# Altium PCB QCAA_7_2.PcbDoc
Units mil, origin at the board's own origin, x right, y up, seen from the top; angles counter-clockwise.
Board outline 636.93 x 714.73 mil, 2 copper layers (Top Layer, Bottom Layer); 42 components, 40 nets, 167 pads, 57 vias.
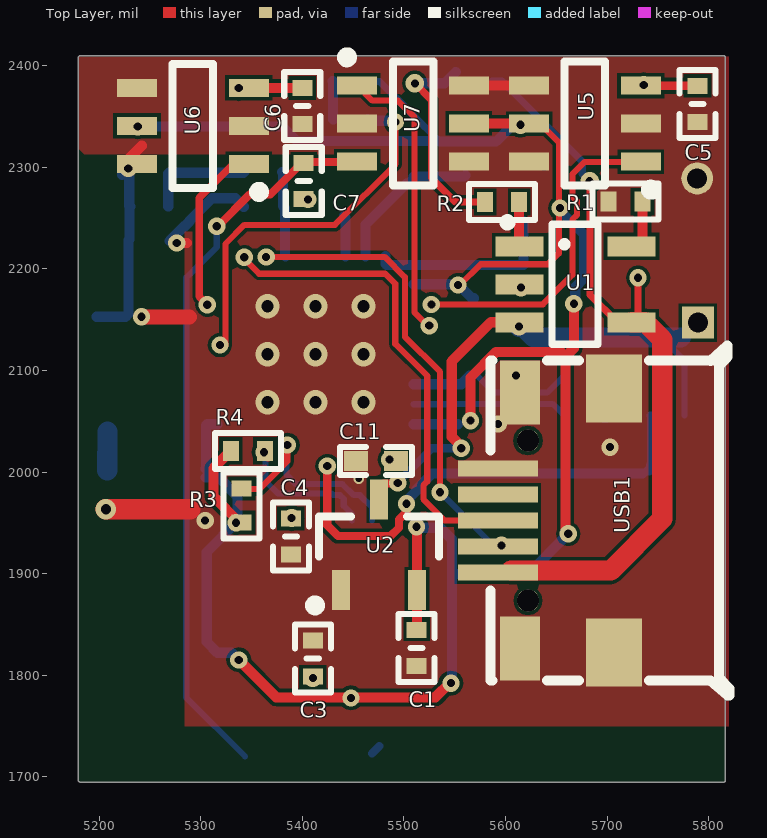
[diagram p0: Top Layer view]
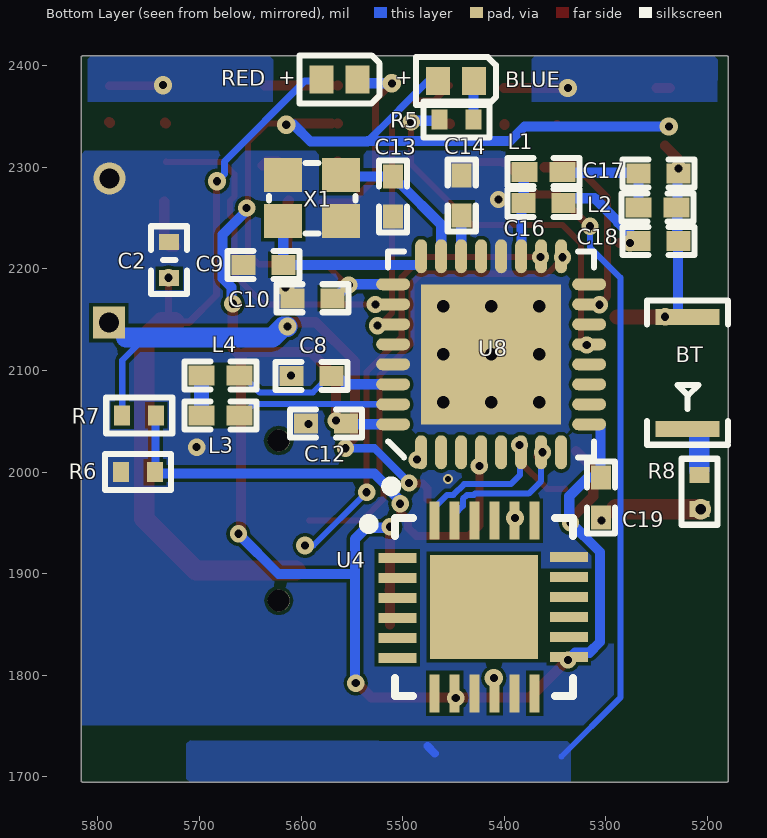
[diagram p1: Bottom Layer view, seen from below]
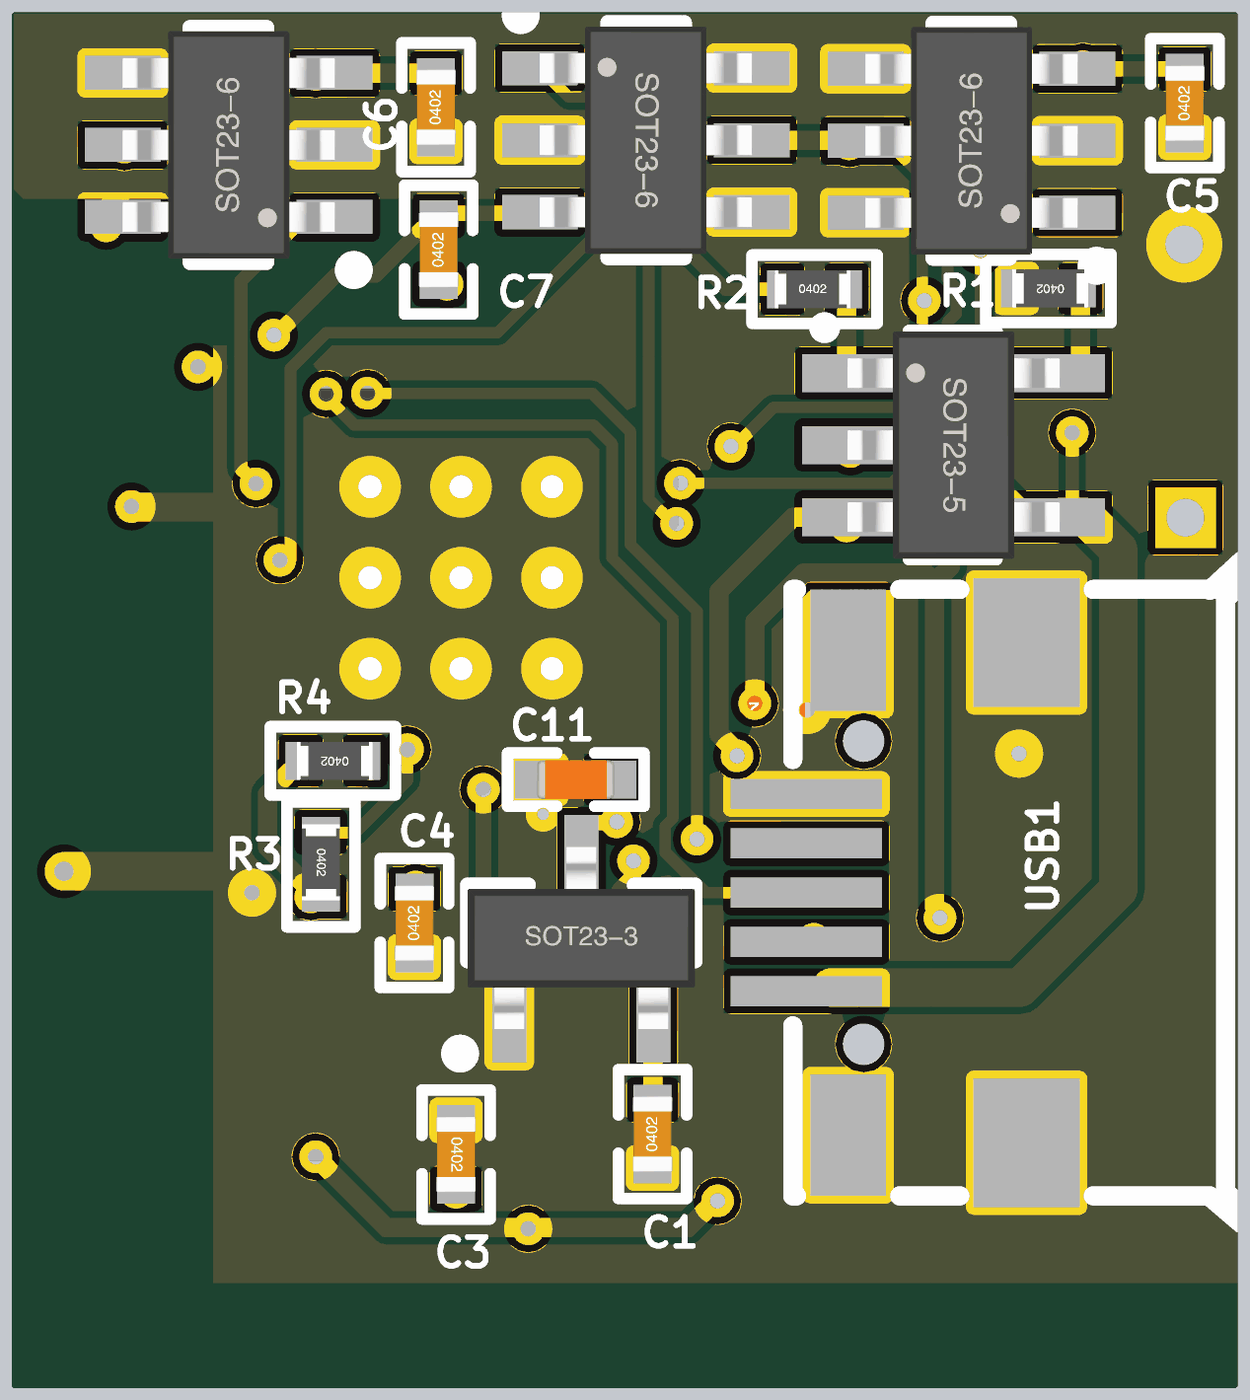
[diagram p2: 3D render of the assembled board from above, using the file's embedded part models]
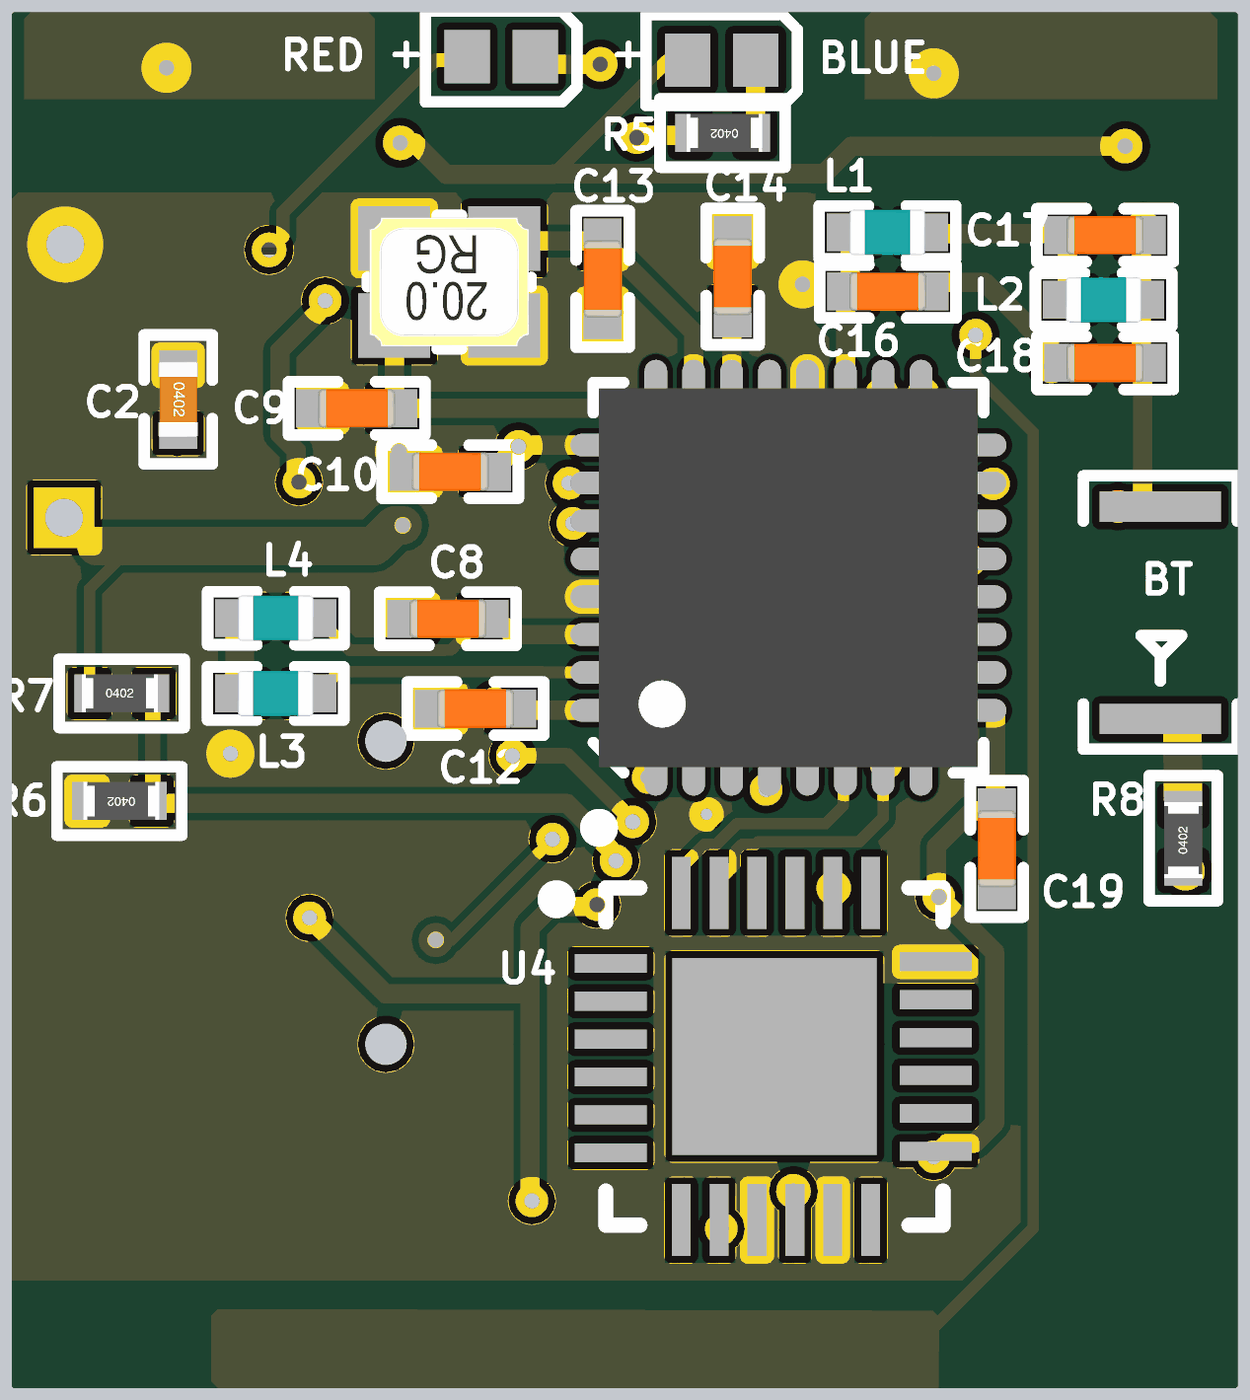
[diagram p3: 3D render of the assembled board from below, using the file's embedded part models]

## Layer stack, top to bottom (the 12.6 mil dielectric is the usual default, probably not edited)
Top Solder: solder mask 0.4, Solder Resist, Dk 3.5
Top Layer: signal copper 1.4
Dielectric 1: dielectric 12.6, FR-4, Dk 4.8
Bottom Layer: signal copper 1.4
Bottom Solder: solder mask 0.4, Solder Resist, Dk 3.5

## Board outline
5179.59,1696.5 5179.59,2408.1 cw(c5181.1,2408.1) 5180.03,2409.17 5180.13,2409.27 cw(c5181.2,2408.2) 5181.2,2409.72 5815,2409.72 cw(c5815,2408.2) 5816.52,2408.2 5816.52,1696.5 cw(c5815,1696.5) 5815,1694.98 5181.1,1694.98 cw(c5181.1,1696.5)

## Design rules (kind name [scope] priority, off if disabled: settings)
Clearance [All] p1: gap=3.5 ignorepadtopadclearanceinfootprint=TRUE except(5: Arc-Via Track-Via)
MinimumSolderMaskSliver [All] p1: minsoldermaskwidth=0
PlaneConnect [All] p1: planeconnectstyle=Direct reliefexpansion=20 reliefentries=4 reliefconductorwidth=10 reliefairgap=10
PolygonConnect [All] p1: connectstyle=Direct reliefconductorwidth=10 reliefentries=4 polygonreliefangle="90 Angle" airgapwidth=10
RoutingVias [All] p1: holewidth=28 width=50 viastyle="Through Hole" minholewidth=3 minwidth=0 maxholewidth=28 maxwidth=50
SilkToSilkClearance [All] p1: silktosilkclearance=0
SilkToSolderMaskClearance [IsPad] p1: minsilkscreentomaskgap=0 clearancetoexposedcopper=TRUE
SolderMaskExpansion [All] p1: expansion=4
Width [All] p1: maxlimit=20 minlimit=6 preferedwidth=10
26 further rules are at their usual default settings.

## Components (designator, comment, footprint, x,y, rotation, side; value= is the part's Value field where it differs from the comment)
BLUE "蓝色" LED2-0R6X1R0 5447.7,2384.9 r180 bottom (schematic designator LED2)
BT "ANT1" BLUETOOTH_ANT 5219.8,2026.92 r90 bottom (schematic designator Bluetooth1)
C1 "1uF" "C 0402_L" 5512.5,1827 r90 top
C2 "1uF" "C 0402_L" 5730,2208.6 r270 bottom
C3 "100nF" "C 0402_L" 5410.4,1816.4 r270 top
C4 "2.2nF" "C 0402_L" 5388.8,1936.6 r90 top
C5 "10uF" "C 0402_L" 5789,2362.5 r90 top
C6 "5uF" "C 0402_L" 5400,2360.4 r90 top
C7 "10uF" "C 0402_L" 5401.4,2286.4 r90 top
C8 "1.0µF" CAPC1005X04L 5589.9,2094.7 r180 bottom value=1.0μF
C9 "12pF" CAPC1005X04L 5637.3,2204 r0 bottom
C10 "100nF" CAPC1005X04L 5588.7,2171.1 r0 bottom
C11 "100nF" CAPC1005X04L 5472.6,2011.1 r180 top
C12 "4.7µF" CAPC1005X04L 5575.6,2048 r0 bottom value=4.7μF
C13 "12pF" CAPC1005X04L 5509.5,2271.2 r270 bottom
C14 "100pF" CAPC1005X04L 5442,2272.4 r90 bottom
C16 "0.8pF" CAPC1005X04L 5361.4,2264.7 r0 bottom
C17 "NC" CAPC1005X04L 5248.5,2293.9 r0 bottom value=0.8pF
C18 "NC" CAPC1005X04L 5248.5,2227.6 r180 bottom value=0.8pF
C19 "100nF" CAPC1005X04L 5304.8,1975.2 r270 bottom
L1 "3.9nH" INDC1005X04L 5361.6,2295.4 r180 bottom
L2 "3nH" INDC1005X04L 5249.3,2260.4 r180 bottom value=3.9nH
L3 "10µH" INDC1005X04L 5679.4,2055.9 r180 bottom value=10μH
L4 "15nH" INDC1005X04L 5679.3,2095 r0 bottom
R1 "2K" "R 0402_L" 5719.1,2266.3 r180 top
R2 "3.3K" "R 0402_L" 5595.7,2265.9 r0 top
R3 "4.7K" "R 0402_L" 5340.2,1968.1 r270 top
R4 "4.7K" "R 0402_L" 5347.4,2020.9 r180 top
R5 "3.3K" "R 0402_L" 5446.3,2347 r0 bottom
R6 "1M" "R 0402_L" 5759.6,2000 r0 bottom
R7 "1M" "R 0402_L" 5760.4,2055.9 r180 bottom
R8 "Res2" "R 0402_L" 5207.9,1979.7 r90 bottom value=0
RED "红色" LED2-0R6X1R0 5562.2,2386.7 r180 bottom (schematic designator LED1)
U1 "HX4054A" SOT23-5N 5668.9,2184.9 r270 top
U2 "XC6206P332MR" SOT23-3L 5475.5,1928.8 r0 top
U4 "MPU6050" MPU6050 5420.3,1867.27 r180 bottom
U5 "TTP223" SOT23-6L 5678.2,2343 r90 top
U6 "TTP223" SOT23-6L 5292.3,2340.8 r90 top
U7 "TTP223" SOT23-6L 5509,2343.3 r270 top
U8 "nRF52810-QCAA" Nordic_QFN50P500X500X90-33N 5413,2116 r90 bottom
USB1 "USB-5P" MICRO-USB-SMD_MICROQTJ 5649.6,1952.4 r90 top
X1 "32MHz" BT-XTAL_2016 5589.2,2269.6 r0 bottom

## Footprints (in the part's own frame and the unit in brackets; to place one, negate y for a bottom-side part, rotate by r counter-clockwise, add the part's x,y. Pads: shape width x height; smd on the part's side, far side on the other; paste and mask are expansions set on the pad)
BLUETOOTH_ANT [mm] "陶瓷表贴蓝牙天线"
  rect 0.4x1.6 smd: 1(0.4,0) 2(3.2,0)
  silkscreen extent 0,-1.02 3.61,1.02
BT-XTAL_2016 [mm]
  rect 0.95x0.85 smd: 1(-0.725,-0.575) 2(0.725,-0.575) 3(0.725,0.575) 4(-0.725,0.575)
  silkscreen extent -1.08,-0.88 1.08,0.88, body extent -1.05,-0.85 1.05,0.85, height 0.56
"C 0402_L" [mm] "无极性贴片电容"
  rect 0.4x0.5 smd: 1(-0.45,0) 2(0.45,0)
  silkscreen extent -0.85,-0.45 0.85,0.45, body extent -0.5,-0.26 0.5,0.26, height 0.53
CAPC1005X04L [mm]
  rect 0.6x0.5 smd: 1(-0.5,0) 2(0.5,0)
  silkscreen extent -0.9,-0.35 0.9,0.35, body extent -0.51,-0.25 0.51,0.25, height 0.5
INDC1005X04L [mm]
  rect 0.65x0.5 smd: 1(-0.475,0) 2(0.475,0)
  silkscreen extent -0.9,-0.35 0.9,0.35, body extent -0.5,-0.3 0.5,0.3, height 0.5
LED2-0R6X1R0 [mm]
  rect 0.6x0.7 smd: 1(-0.45,0) 2(0.45,0)
  silkscreen extent -1,-0.6 1,0.6
MICRO-USB-SMD_MICROQTJ [mm]
  rect 0.4x2 smd: 1(-1.3,1.452) 2(-0.65,1.452) 3(0,1.452) 4(0.65,1.452) 5(1.3,1.452)
  rect 1.7x1.4 smd: 5(-3.3,-1.452) 5(3.3,-1.452)
  rect 1.6x1 smd: 5(-3.2,0.902) 5(3.2,0.902)
  round 0.55 hole 0.55 unplated: ""(-2,0.698) ""(2,0.698)
  silkscreen extent -4.37,-4.34 4.38,1.63
MPU6050 [mm] "QFN, 24-Leads, Body 4.00x4.00mm, Pitch 0.50mm, Thermal Pad 2.70x2.60mm, IPC Medium Density"
  rect 0.95x0.25 smd: 1(-2.159,1.23) 2(-2.159,0.73) 3(-2.159,0.23) 4(-2.159,-0.27) 5(-2.159,-0.77) 6(-2.159,-1.27) 13(2.127,-1.25) 14(2.127,-0.75) 15(2.127,-0.25) 16(2.127,0.25) 17(2.127,0.75) 18(2.127,1.25)
  rect 0.25x0.95 smd: 7(-1.23,-2.159) 8(-0.73,-2.159) 9(-0.23,-2.159) 10(0.27,-2.159) 11(0.77,-2.159) 12(1.27,-2.159) 19(1.27,2.159) 20(0.77,2.159) 21(0.27,2.159) 22(-0.23,2.159) 23(-0.73,2.159) 24(-1.23,2.159)
  rect 2.7x2.6 smd: 25(0,0)
  silkscreen extent -3,-2.22 2.22,2.23, body extent -2.08,-2.07 2.07,2.08, height 0.9
Nordic_QFN50P500X500X90-33N [mm]
  oval 0.85x0.3 smd mask+0.076: 1(-2.45,1.75) 2(-2.45,1.25) 3(-2.45,0.75) 4(-2.45,0.25) 5(-2.45,-0.25) 6(-2.45,-0.75) 7(-2.45,-1.25) 8(-2.45,-1.75) 17(2.45,-1.75) 18(2.45,-1.25) 19(2.45,-0.75) 20(2.45,-0.25) 21(2.45,0.25) 22(2.45,0.75) 23(2.45,1.25) 24(2.45,1.75)
  oval 0.3x0.85 smd mask+0.076: 9(-1.75,-2.45) 10(-1.25,-2.45) 11(-0.75,-2.45) 12(-0.25,-2.45) 13(0.25,-2.45) 14(0.75,-2.45) 15(1.25,-2.45) 16(1.75,-2.45) 25(1.75,2.45) 26(1.25,2.45) 27(0.75,2.45) 28(0.25,2.45) 29(-0.25,2.45) 30(-0.75,2.45) 31(-1.25,2.45) 32(-1.75,2.45)
  rect 3.5x3.5 smd: 33(0,0)
  silkscreen extent -3.42,-2.57 2.57,2.63, body extent -2.5,-2.5 2.5,2.5, height 0.9
"R 0402_L" [mm] "1/16W贴片电阻"
  rect 0.4x0.5 smd: 1(-0.4,0) 2(0.45,0)
  silkscreen extent -0.8,-0.45 0.85,0.45, body extent -0.5,-0.25 0.5,0.25, height 0.3
SOT23-3L [mm] "3x1.3x1mm(长宽高)"
  rect 0.45x1 smd: 1(-0.95,-1.143) 2(0.95,-1.143) 3(0,1.125)
  silkscreen extent -1.72,-1.65 1.5,0.7, body extent -1.5,-1.2 1.5,1.2, height 1.05
SOT23-5N [mm] "3x1.6x1.1mm(长宽高)"
  rect 0.5x1.2 smd: 1(-0.95,-1.4) 2(0,-1.4) 3(0.95,-1.4) 4(0.95,1.4) 5(-0.95,1.4)
  silkscreen extent -1.63,-1.78 1.5,0.56, body extent -1.5,-1.4 1.5,1.4, height 1.15
SOT23-6L [mm] "3x1.6x1.1mm(长宽高)"
  rect 0.45x1 smd: 1(-0.95,-1.397) 2(0,-1.397) 3(0.95,-1.397) 4(0.95,1.397) 5(0,1.397) 6(-0.95,1.397)
  silkscreen extent -1.77,-1.78 1.55,0.51, body extent -1.5,-1.4 1.5,1.4, height 1.15

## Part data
BLUE RED: library part LED-SMD, "贴片LED"
BT: library part BLUETOOTH_ANT, "PCB板载天线"
C1 C2 C3 C4 C5 C6 C7: library part C, "无极性贴片电容"
C8: library part C0603-1μ0, "Capacitor, X7R, ±10%"
C9 C13: library part C0402-12p, "Capacitor, NP0, ±2%"
C10 C11 C19: library part C0402-100n, "Capacitor, X7R, ±10%"
C12: library part C0603-4μ7, "Capacitor, X5R, ±10%"
C14: library part C0402-100p, "Capacitor, NP0, ±5%"
C16 C17 C18: library part C0402-0.8p, "Capacitor, NP0, ±5%"
L1 L2: library part L0402-3n9, "High frequency chip inductor ±5%"
L3: library part L0603-10μ, "Chip inductor, IDC,min = 50 mA, ±20%"
L4: library part L0402-15n, "High frequency chip inductor ±10%"
R1 R2 R3 R4 R5 R6 R7: library part R, "贴片电阻"
R8: "Resistor"
U1: library part MCP73831/2, "Li-on Charging IC"
U2: "DC-DC Linear IC / Cheap"
U4: "Three-axis MEMS IC"
U5 U6 U7: library part TTP223E-BA6, "Touching switch IC"
U8: "Multi-protocol Bluetooth Low Energy, ANT and 2.4GHz proprietary system-on-chip", Manufacturer="Nordic Semiconductor"
USB1: "微型USB母座"
X1: library part XTAL_SMD2016_32MHz_8pF_General, "XTAL SMD 2016, 32MHz, Cl=8pF, Total Tol: ±40ppm"

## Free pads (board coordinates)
  rect 31.5x31.5 hole 19.68: 14(5789.3,2147.2)
  round 31.5 hole 19.68: 15(5788.7,2289.1)

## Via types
v1: diameter 17, hole 8, Top Layer to Bottom Layer, 36 vias
v2: diameter 24, hole 12, Top Layer to Bottom Layer, 9 vias
v3: diameter 18, hole 8, Top Layer to Bottom Layer, 8 vias
v4: diameter 17.72, hole 7.87, Top Layer to Bottom Layer, tented both sides, 2 vias
v5: diameter 20, hole 10, Top Layer to Bottom Layer, 1 vias
v6: diameter 10, hole 6, Top Layer to Bottom Layer, 1 vias

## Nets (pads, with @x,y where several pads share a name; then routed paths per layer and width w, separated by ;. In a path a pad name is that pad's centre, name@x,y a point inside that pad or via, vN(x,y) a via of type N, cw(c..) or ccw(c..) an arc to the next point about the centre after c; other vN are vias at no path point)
+3.3V: BLUE.1 C1.2 C10.1 C12.1 C19.1 R3.2 R4.2 U2.2 U4.8 U4.13 U5.5 U6.5 U7.5 U8.9 U8.25 U8.32 | length 2387
  Top Layer w6: v1(5553.2,2184.2) 5555.2,2184.2 5575.6,2204.6 5641.7,2204.6 5652.5,2215.4 5652.5,2324.53 5634.03,2343 U5.5
  Top Layer w10: R4.2 5312.5,2003.72 5312.5,1976.12 R3.2@5338.23,1950.39 ; v1(5337.5,1815.2) 5374.4,1778.3 5531,1778.3 v1@5545.4,1792.7 ; v1(5512.5,1946.2) 5512.75,1945.95 U2.2@5512.75,1886.8 ; C1.2@5512.6,1849.91 5512.75,1850.06 5512.75,1883.65 U2.2 ; U7.5 U7.5@5564.15,2343.15 ; v1(5565.6,2050.7) 5565.6,2093.08 5590.9,2118.38 5654.42,2118.38 5659.1,2113.7 ; U7.5@5570.45,2343.15 U5.5@5614.7,2343.15 ; v1@5659.1,1944.1 5659.1,2113.7 ; v1(5667.3,2165.7) 5667.3,2121.9 5659.1,2113.7
  Bottom Layer w7: BLUE.1@5466.32,2384.43 5475.97,2384.43 5498.8,2361.6 ; 5498.84,2361.6 5508.8,2351.64 ; 5508.8,2351.6 5534.5,2325.9 5534.9,2325.5
  Bottom Layer w10: v3(5238.1,2340.2) 5380.23,2340.2 5394.53,2325.9 5534.5,2325.9 ; C19.1 5317.61,1994.88 5336.1,1976.4 5336.1,1951.67 5305.9,1921.47 5305.9,1832.76 5316.41,1822.25 5330.45,1822.25 v1(5337.5,1815.2) ; C19.1@5304.9,2003.29 5305.37,2003.75 5305.37,2046.27 5306.21,2047.1 U8.9 ; U8.32 C12.1@5553.25,2047.1 ; U8.25 v1@5553.2,2184.9 ; v1(5512.5,1946.2) 5513.4,1945.3 5536,1945.3 5547.2,1934.1 5547.2,1899.8 ; 5534.9,2325.5 5590.8,2325.5 5607.2,2341.9 v3(5614.7,2341.9) ; v1@5547.2,1792.3 5547.2,1899.8 ; v1(5553.2,2184.2) 5553.95,2184.2 5567.05,2171.1 C10.1 ; v1(5653.7,2259.9) 5653.7,2257.5 5677.3,2233.9 5677.3,2190.64 5668.64,2181.98 5668.64,2167.04 v1(5667.3,2165.7) ; v1(5661.8,1939.3) 5622.3,1899.8 5547.2,1899.8
  other v1: 5447.9,1777.8 5546.3,1792.3 5334.9,1950.2
blue: R5.2 U8.13 | length 367.6
  Top Layer w6: v1@5324.4,2124.9 5324.4,2224.7 5343,2243.3 5431.97,2243.3 5491.8,2303.13 v1(5491.8,2344.6)
  Bottom Layer w10: R5.2 5465.21,2345.8 5488.57,2345.8 v1@5489.55,2346.78
  other v1: 5318.9,2125.1
DEC1: C11.1 U8.1
  other v1: 5485.9,2012.3
DEC2: U8.21
DEC3: C14.1 U8.22 | length 40.2
  Bottom Layer w10: C14.1@5441.1,2252.11 5442.53,2250.69 U8.22
DEC4: C8.2 L4.1 U8.30 | length 163.3
  Bottom Layer w6: C8.2 5572.18,2094.7 5588.38,2078.5 5591.6,2078.5 5591.74,2078.36 5641,2078.36 5657.65,2095 L4.1 L4.1@5660.3,2094.7
  Bottom Layer w10: U8.30 5556.47,2086.47 C8.2@5564.8,2094.8
Detection: R6.1 R7.2 U8.4 | length 468.2
  Top Layer w8: v1(5424.62,2006.02) 5424.62,1947.38 5435,1937 5486.7,1937 5495,1945.3 5495,1953.45 5502.6,1961.05 v1(5502.6,1968.9)
  Bottom Layer w8: R7.2 5743.31,2055.27 R6.1@5743.31,2007.02
  Bottom Layer w10: v1@5499.6,1968.3 5499.6,1968.74 5512.4,1981.54 5512.4,1983.16 5527.94,1998.7 5734.99,1998.7 ; R6.1@5741.06,2001.56 5743.31,2003.81 R6.1@5743.31,2007.02
GND: BT.2 C1.1 C2.1 C3.1 C4.1 C5.1 C6.1 C7.1 C8.1 C9.2 C10.2 C11.2 C12.2 C13.2 C14.2 C16.1 C17.1 C18.1 C18.2 C19.2 L2.2 pad.15 R1.2 R6.2 R8.1 U1.2 U2.1 U4.9 U4.11 U4.18 U5.2 U5.4 U5.6 U6.2 U6.4 U6.6 U7.2 U7.4 U7.6 U8.20 U8.29 U8.33 USB1.5 X1.2 X1.4 | length 535.8
  Top Layer w10: U6.6@5229.75,2308.95 5242,2321.2 ; U6.4 U6.4@5250.1,2378.2 ; v1(5276.4,2225.5) 5286.6,2225.5 ; U6.2 U6.2@5348.24,2341.74 ; C6.1@5400,2341.74 C6.1 ; U7.2@5453.38,2342.68 U7.2 ; U7.4 U7.4@5564.15,2305.75 ; U7.6 U7.6@5564.15,2380.55 ; U7.6@5570.45,2380.55 5623.05,2380.55 U5.4 U5.4@5635.8,2380.4 ; U5.6@5623.05,2305.75 U5.6 ; U5.6@5624.5,2304.3 U5.6 ; U5.6@5637.89,2301.74 5634.03,2305.6 U5.6 ; U5.2 U5.2@5734.09,2343.89 ; C5.1@5788.11,2343.89 C5.1
  Top Layer w15: v1(5241.8,2153) 5242.1,2152.7 5288.9,2152.7
  Top Layer w20: v5(5206.7,1963.5) 5290,1963.5
  Bottom Layer w10: BT.2@5197.37,2152.9 BT.2 5226.14,2152.9 5229.01,2155.77 5229.01,2228.5 5229.81,2229.29 5229.81,2260.51 5230.6,2261.3 5229.71,2262.19 5229.71,2293.01 C17.1 ; C17.1@5222.6,2292.7 v1(5228.7,2298.8) ; C18.1@5269.28,2227.6 5283.74,2242.06 5284.32,2242.06 5289.3,2247.04 5289.3,2247.61 5311.19,2269.5 5334.02,2269.5 C16.1@5342.31,2261.2
  other v1: 5304.4,1952.4 5702.9,2024.6 5592.8,2047.3 5610.2,2095 5615.3,2181.6 5405.7,2268.4
  other v2: 5365.76,2068.76 5413,2068.76 5460.24,2068.76 5365.76,2116 5413,2116 5460.24,2116 5365.76,2163.24 5413,2163.24 5460.24,2163.24
  other v6: 5455.6,1993.1
NetBluetooth1_1: BT.1 R8.2 | length 37.7
  Bottom Layer w20: R8.2@5208.12,2002.01 BT.1@5208.33,2039.69
NetC3_2: C3.2 U4.10
  other v3: 5410.4,1797.3
NetC4_2: C4.2 U4.20
  other v3: 5389.5,1954.8
NetC5_2: C5.2 U5.3 | length 55.9
  Top Layer w8: U5.3 5733.29,2380.31 5788.91,2380.31 C5.2
  other v3: 5736.1,2380.9
NetC6_2: C6.2 U6.3 | length 53
  Top Layer w10: U6.3 U6.3 5400.26,2378.16 C6.2@5400.3,2378.11
  other v3: 5337.5,2378
NetC7_2: C7.2 U7.3 | length 730.7
  Top Layer w8: v1@5317.4,2242.5 5348.07,2273.17 5368.49,2273.17 5399.43,2304.11 C7.2 ; C7.2@5402,2304.71 5402.6,2305.31 5453.41,2305.31 U7.3
  Bottom Layer w6: v1(5315.8,2242) 5315.8,2221.4 5285.8,2191.4 5285.8,1778.1 5343.8,1720.1
  Bottom Layer w8: 5468.5,1723.2 5475.8,1730.5
NetC16_2: C16.2 L1.1 U8.19 | length 84.3
  Bottom Layer w10: L1.1 5380.99,2294.71 5380.99,2261.89 5381.69,2261.2 5383.13,2259.76 5383.13,2212.8 U8.19
NetC17_2: C17.2 L1.2 L2.1 | length 108
  Bottom Layer w10: L2.1@5268,2261.3 5268.09,2261.39 5268.09,2293.81 C17.2 5268.94,2294.65 5342.15,2294.65 L1.2
NetL3_1: L3.1 L4.2 | length 39.1
  Bottom Layer w10: L4.2 L4.2@5698.05,2094.95 ; L3.1@5698.05,2055.95 L3.1
  Bottom Layer w15: L3.1@5698.05,2055.95 L4.2@5698.05,2094.95
NetL3_2: L3.2 U8.31 | length 156.1
  Bottom Layer w6: U8.31 5540.74,2066.79 5541.15,2067.2 5646.45,2067.2 5657.75,2055.9 L3.2
NetLED1_2: R2.1 RED.2 | length 207.5
  Top Layer w7: v3(5510.8,2382.7) 5527,2366.5 5527,2289.4 5550.5,2265.9 R2.1
  Bottom Layer w10: v3(5510.8,2382.7) 5539.9,2382.7 RED.2@5550.97,2393.77
NetLED2_2: BLUE.2 R5.1 | length 38.1
  Bottom Layer w10: BLUE.2 5430.27,2384.62 5430.27,2347.29 R5.1
NetR1_1: R1.1 U1.5 | length 52
  Top Layer w10: U1.5 5730.01,2222.3 5734.85,2227.14 R1.1
NetR2_2: R2.2 U1.1 | length 45.5
  Top Layer w10: R2.2@5612.2,2267.11 R2.2 5613.41,2222.67 U1.1
P0.05/AIN3: U8.5
P0.10: U8.8
P0.12: U8.10
P0.14: U8.11
P0.15: U8.12
P0.18: U8.14
P0.30/AIN6: U8.28
Q1: U6.1 U8.15 | length 185.5
  Top Layer w7: v1(5306.5,2164.8) 5298.6,2172.7 5298.6,2270 5332,2303.4 U6.1
  Top Layer w10: U6.1 5350.6,2300.1 U6.1@5360.4,2300.1
Q2: U5.1 U8.26 | length 326.1
  Top Layer w6: v1(5527,2165.1) 5636.64,2165.1 5665.8,2194.26 5665.8,2248.67 5670.2,2253.07 5670.2,2266.73 5665.8,2271.13 5665.8,2293.34 5677.86,2305.4 5733,2305.4 U5.1
Q3: U7.1 U8.27 | length 292.4
  Top Layer w6: U7.1 5469,2365.7 5494.03,2365.7 5510.5,2349.23 5510.5,2156.97 5523.27,2144.2 v1(5525,2144.2)
  Top Layer w7: U7.1 U7.1@5464.83,2380.7
SCL: R4.1 U4.23 U8.7 | length 141.5
  Top Layer w10: R4.1@5363.25,2018.5 R4.1@5366.13,2015.63
  Bottom Layer w6: U8.7 5363.79,1991.21 5376.2,1978.8 5428.77,1978.8 5430.09,1977.48 5436.97,1977.48 5440.78,1973.67 5440.78,1966.79 5449.04,1958.52 U4.23
  other v1: 5362.4,2019.6
SDA: R3.1 U4.24 U8.6 | length 205.6
  Top Layer w6: R3.1 5340.55,1983.5 5358,1983.5 5385.2,2010.7 v1(5385.2,2026.7)
  Bottom Layer w6: U8.6 5384.58,2018.43 5384.58,1997.42 5393.7,1988.3 5439.58,1988.3 5450.28,1977.6 5450.28,1977.48 5456.65,1977.48 5468.73,1965.4 U4.24
SWDCLK: U8.17 USB1.3 | length 469
  Top Layer w6: v1(5342.9,2211.5) 5342.9,2209.97 5357.57,2195.3 5481.6,2195.3 5491.5,2185.4 5491.5,2126.3 5523,2094.8 5523,1990.93 5519.1,1987.03 5519.1,1973.37 5540.07,1952.4 USB1.3
SWDIO: U8.18 USB1.2 | length 452.1
  Top Layer w6: v1(5364.4,2211.8) 5481.1,2211.8 5501,2191.9 5501,2133.2 5535.6,2098.6 5535.6,1981.83 v1@5535.83,1981.6
  Bottom Layer w6: v1(5535.6,1980.2) 5588,1927.8 v4(5596.2,1927.8)
  Bottom Layer w10: v4(5596.2,1927.8) v4@5596.36,1927.96
USB_Power: C2.2 RED.1 U1.4 USB1.1 | length 738.7
  Top Layer w7: v3(5682.8,2286.3) 5683.3,2285.8 5683.3,2174.44 5710.24,2147.5 U1.4 5724.16,2147.5 5730.5,2153.84 v1(5730.5,2191.3)
  Top Layer w20: USB1.1@5605.35,1903.12 5703.48,1903.12 5754.4,1954.03 5754.4,2130.58 5737.48,2147.5 U1.4@5724.16,2147.5
  Bottom Layer w7: RED.1@5586.57,2384.87 5596.47,2384.87 5675.6,2305.75 5675.6,2293.5 v3(5682.8,2286.3)
VBAT: pad.14 R7.1 U1.3 U2.3 | length 531.4
  Top Layer w8: U2.3 5475.5,1983.92 5480.36,1988.78 5493.48,1988.78 v1(5493.9,1989.2)
  Top Layer w10: v1@5556.39,2021.79 5556.39,2025.41 5547.1,2034.69 5547.1,2109 5585.6,2147.5 U1.3
  Bottom Layer w6: 5753.8,2132.47 5776.15,2110.11 R7.1
  Bottom Layer w8: v1(5493.9,1989.2) 5493.9,1989.6 5527.8,2023.5 v1(5556.4,2023.5)
  Bottom Layer w20: v4(5613.4,2143.2) 5617.6,2143.2 5628.33,2132.47 5753.8,2132.47 5772.51,2132.47
XC1: C13.1 U8.23 X1.1 | length 150.9
  Bottom Layer w10: U8.23 5462.21,2243.6 5502.69,2284.07 5504.66,2284.07 5509.5,2288.92 C13.1 5559.3,2290.89 X1.1
XC2: C9.1 U8.24 X1.3 | length 186.7
  Bottom Layer w10: U8.24 5481.9,2204.84 5482.73,2204 C9.1 5617.61,2246.83 X1.3
pads on no net: U4.1 U4.2 U4.3 U4.4 U4.5 U4.6 U4.7 U4.12 U4.14 U4.15 U4.16 U4.17 U4.19 U4.21 U4.22 U4.25 U8.2 U8.3 U8.16 USB1. USB1.4

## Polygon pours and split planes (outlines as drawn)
GND on Bottom Layer "Bottom Layer-GND" (solid, pour order 68): 5180.2,2316.2 5818.7,2316.2 5819.5,2315.4 5816.6,2312.5 5816.6,1750.9 5183,1750.9 5180.9,1753
NetC5_2 on Bottom Layer "Bottom Layer-NetC5_2" (solid, pour order 60): 5627.73,2409.59 5809.96,2409.99 5809.96,2364.5 5627.89,2364.5
NetC6_2 on Bottom Layer "Bottom Layer-NetC5_2" (solid, pour order 56): 5190.13,2409.57 5373.3,2409.97 5373.3,2364.5 5190.28,2364.5
NetC7_2 on Bottom Layer "Bottom Layer-NetC5_2" (solid, pour order 52): 5334.74,1735.29 5712.9,1736.11 5712.9,1694.81 5334.88,1694.81
no net on Bottom Layer "Bottom Layer-No Net 1" (solid, pour order 30): 5474.76,2574.93
no net on Bottom Layer "Bottom Layer-No Net 1" (solid, pour order 28): 5475.16,2546.43
no net on Bottom Layer "Bottom Layer-No Net 2" (solid, pour order 26): 5557.19,2426.67
GND on Top Layer "Top Layer-GND" (solid, pour order 64): 5180.7,2409 5819.9,2409 5819.9,1749.7 5183.2,1749.7 5179.8,1753.1
no net on Top Layer "Top Layer-No Net" (solid, pour order 42): 5639.4,2417.4

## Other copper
Top Layer:
  pour cut-out: 5180,2313.8 5180.9,2312.9 5399.3,2312.9 5399.3,2245.4 5390.7,2236.8 5284.1,2236.8 5284.1,1693.1 5282.4,1694.8 5179.5,1694.8 5179.5,2311.6 5180,2312.1
Bottom Layer:
  pour cut-out: 5179,2372.25 5179.9,2371.35 5398.3,2371.35 5398.3,2303.85 5389.7,2295.25 5286.1,2295.25 5286.1,1754.55 5283.1,1751.55 5281.4,1753.25 5178.5,1753.25 5178.5,2370.05 5179,2370.55

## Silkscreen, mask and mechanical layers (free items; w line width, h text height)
Mechanical 1:
  lines w3: 5815,1935.2 5815,2408.2 5181.2,2408.2 5181.1,2408.1 5181.1,1696.5 5815,1696.5 5815,1937.21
